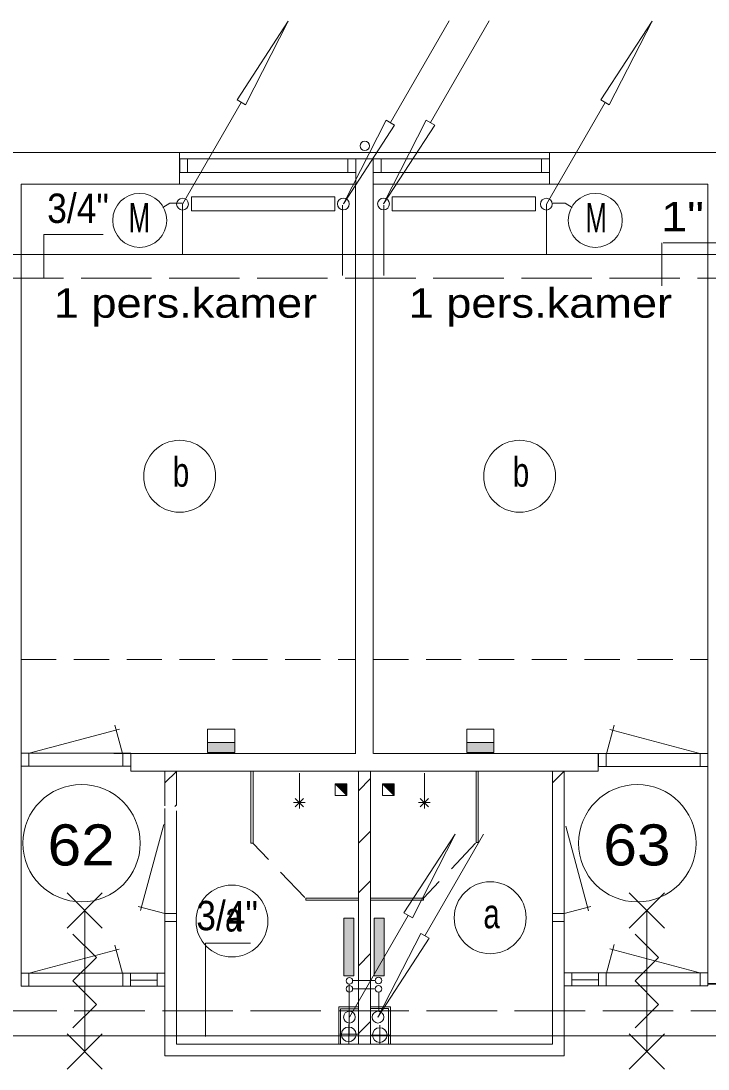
# Model space of a CAD drawing. Extents: x 295824 to 414724, y 24924 to 109024.
# Drawn here: x 308090 to 313941, y 39720 to 48648 of the extents above; entities that cross this region are included whole.
import ezdxf
from ezdxf.enums import TextEntityAlignment as Align

# ---------------------------------------------------------------- set-up
doc = ezdxf.new("R2010")
doc.units = 0
doc.header["$LTSCALE"] = 100
for name, pattern in [('DOT_DASHED', [7.7, 5, -1.2, 0.3, -1.2]), ('LONG_DASHED', [7.5, 6, -1.5]), ('MEDIUM_DASHED', [4.5, 3, -1.5])]:
    doc.linetypes.add(name, pattern=pattern)
doc.layers.add('16', color=7, linetype='Continuous', lineweight=13)
doc.layers.add('61', color=7, linetype='Continuous', lineweight=13)

msp = doc.modelspace()

# ---------------------------------------------------------------- hatches: boundary and pattern name
at = {"layer": '16'}
for points in [[(309911.3, 42415.9), (309679.8, 42415.9), (309679.8, 42502.4), (309911.3, 42502.4)], [(312117.3, 42415.9), (311885.8, 42415.9), (311885.8, 42502.4), (312117.3, 42502.4)], [(310838.6, 41005.7), (310924, 41005.7), (310924, 40513.5), (310838.6, 40513.5)], [(311097.8, 41005.7), (311183.2, 41005.7), (311183.2, 40513.5), (311097.8, 40513.5)]]:
    msp.add_hatch(color=256, dxfattribs=at).paths.add_polyline_path(points)
at = {"layer": '61'}
for points in [[(310864.9, 42048.6), (310764.9, 42148.6), (310864.9, 42148.6)], [(311267.9, 42048.6), (311167.9, 42148.6), (311267.9, 42148.6)]]:
    msp.add_hatch(color=256, dxfattribs=at).paths.add_polyline_path(points)

# ---------------------------------------------------------------- linework, layer by layer
at = {"layer": '16'}
for p, q in [((311735.8, 48648), (311235.8, 47782)), ((312077.5, 48648), (311577.5, 47782)), ((309465.8, 47087.9), (309965.8, 47953.9)), ((312564.3, 47087.9), (313064.3, 47953.9)), ((309466.3, 47084.3), (309466.3, 46658)), ((312564.8, 47084.3), (312564.8, 46658)), ((313547, 46391.6), (313547, 46759.1)), ((313558.7, 46759.1), (314063.8, 46759.1)), ((303410.7, 46658), (326194, 46658)), ((309466.3, 46658), (325376.7, 46658)), ((309679.8, 42502.4), (309679.8, 42616.3)), ((311885.8, 42502.4), (311885.8, 42616.3)), ((312030.4, 41720.5), (311530.4, 40854.5)), ((310887.4, 40162.2), (311387.4, 41028.2)), ((311106.2, 40474.7), (310914.5, 40474.7)), ((310885.9, 40002.8), (310885.9, 40439.3)), ((326194, 40002.8), (302570.9, 40002.8))]:
    msp.add_line(p, q, dxfattribs=at)
at = {"layer": '16', "linetype": 'LONG_DASHED'}
for p, q in [((310827, 47078.4), (310827, 46458)), ((311180.5, 47078.4), (311180.5, 46458)), ((304851.7, 46458), (326394, 46458)), ((310914.6, 40403.9), (311106.1, 40403.9)), ((311137.1, 40214.6), (311137.1, 40378.2)), ((326394, 40214.6), (302769.9, 40214.6))]:
    msp.add_line(p, q, dxfattribs=at)
at = {"layer": '16'}
for points in [[(310365.8, 48646.9), (310001.8, 47932.9), (309929.8, 47974.9)], [(313464.3, 48646.9), (313100.3, 47932.9), (313028.3, 47974.9)], [(310835.8, 47089), (311199.8, 47803), (311271.8, 47761)], [(311177.5, 47089), (311541.5, 47803), (311613.5, 47761)], [(309542.9, 47031.2), (310762.2, 47031.2), (310762.2, 47149.1), (309542.9, 47149.1)], [(311251.1, 47031.2), (312470.5, 47031.2), (312470.5, 47149.1), (311251.1, 47149.1)], [(309911.3, 42415.9), (309679.8, 42415.9), (309679.8, 42502.4), (309911.3, 42502.4)], [(312117.3, 42415.9), (311885.8, 42415.9), (311885.8, 42502.4), (312117.3, 42502.4)], [(311787.4, 41721.2), (311423.4, 41007.2), (311351.4, 41049.2)], [(310838.6, 41005.7), (310924, 41005.7), (310924, 40513.5), (310838.6, 40513.5)], [(311097.8, 41005.7), (311183.2, 41005.7), (311183.2, 40513.5), (311097.8, 40513.5)], [(311130.4, 40161.5), (311494.4, 40875.5), (311566.4, 40833.5)]]:
    msp.add_lwpolyline(points, close=True, dxfattribs=at)
for points in [[(309462.5, 47094.6), (309356.5, 47094.6), (309297, 47060.2)], [(312619.9, 47094.6), (312725.9, 47094.6), (312785.4, 47060.2)], [(308284.5, 46462.7), (308284.5, 46830.2), (308789.6, 46830.2)], [(309911.3, 42502.4), (309911.3, 42616.3), (309679.8, 42616.3)], [(312117.3, 42502.4), (312117.3, 42616.3), (311885.8, 42616.3)], [(309662, 39996.4), (309662, 40792.7), (310044.6, 40792.7)]]:
    msp.add_lwpolyline(points, dxfattribs=at)
for centre, radius in [((309101.4, 46949.2), 229.9), ((312981, 46949.2), 229.9), ((309465.7, 47087.6), 50), ((310835.8, 47089.3), 50), ((311177.5, 47089.3), 50), ((312564.3, 47087.6), 50), ((310886.7, 40471.7), 27.9), ((311134.1, 40474.6), 27.9), ((310886.7, 40403.9), 27.9), ((311134.1, 40403.9), 27.9), ((310887.4, 40161.9), 50), ((311130.4, 40161.8), 50)]:
    msp.add_circle(centre, radius, dxfattribs=at)
at = {"layer": '61'}
for p, q in [((301828.9, 47527.9), (333452, 47527.9)), ((309440.9, 47257.3), (309440.9, 47527.3)), ((312589.9, 47257.3), (312589.9, 47527.3)), ((313820.3, 47527.9), (333174.1, 47527.9)), ((309441.7, 47472.1), (310940.7, 47472.1)), ((309441.7, 47358.1), (309441.7, 47472.1)), ((309508.7, 47358.1), (309508.7, 47471.5)), ((310873.7, 47472.1), (312589.7, 47472.1)), ((310873.7, 47358.5), (310873.7, 47472.1)), ((310940.7, 47359.1), (310940.7, 47472.1)), ((310940.9, 47257.3), (310940.9, 47472.1)), ((311089.9, 47257.3), (311089.9, 47472.1)), ((311090.7, 47358.1), (311090.7, 47472.1)), ((311157.7, 47358.1), (311157.7, 47471.5)), ((312522.7, 47358.5), (312522.7, 47471.5)), ((312589.7, 47359.1), (312589.7, 47472.1)), ((309441.7, 47358.1), (310939.8, 47358.1)), ((311090.7, 47358.1), (312588.8, 47358.1)), ((308090.1, 40536.9), (308090.1, 47257.9)), ((313940.1, 40532.9), (313940.1, 47257.9)), ((308160.8, 42409.2), (308928.1, 42614.8)), ((308955.3, 42407.1), (308890.3, 42649.8)), ((313077.1, 42405.1), (313142.2, 42647.8)), ((313871.7, 42407.2), (313104.4, 42612.8)), ((308158.2, 42299.1), (308158.2, 42409.1)), ((308958.2, 42299.1), (308958.2, 42409.1)), ((309025.2, 42299.1), (309025.2, 42409.1)), ((310940.8, 42407.9), (308880.8, 42407.9)), ((311090.8, 42407.9), (313940.1, 42407.9)), ((311090.8, 42407.9), (313033.3, 42407.9)), ((313007.3, 42297.1), (313007.3, 42407.1)), ((313074.3, 42297.1), (313074.3, 42407.1)), ((313874.3, 42297.1), (313874.3, 42407.1)), ((313940.2, 42297.4), (313940.2, 42407.8)), ((309023.1, 42299.4), (308092.3, 42299.4)), ((309026.1, 42257.9), (312616.2, 42257.9)), ((309315.9, 41961), (309315.9, 42257.9)), ((309315.9, 42157.2), (309416.3, 42257.6)), ((309414.6, 41963.8), (309414.6, 42257.9)), ((310048.5, 41644.6), (310048.5, 42253)), ((310066.5, 41644.6), (310066.5, 42253)), ((310461.4, 42039.2), (310461.4, 42239.2)), ((310965.8, 42257.9), (310965.8, 41262.7)), ((311065.8, 42257.9), (311065.8, 41409)), ((311525.9, 42039.2), (311525.9, 42239.2)), ((311966.4, 41650.7), (311966.4, 42255.5)), ((311984.4, 41650.7), (311984.4, 42255.5)), ((312616.2, 41984), (312616.2, 42258.3)), ((312616.4, 42157.2), (312716.8, 42257.6)), ((312716, 41992.3), (312716, 42257.9)), ((313009.4, 42297.4), (313940.2, 42297.4)), ((310966.3, 42093), (311064.8, 42191.5)), ((309400.3, 41955.2), (309414.9, 41969.9)), ((310511.4, 41989.2), (310411.4, 41989.2)), ((310496.8, 42024.5), (310426.1, 41953.8)), ((310496.8, 41953.8), (310426.1, 42024.5)), ((310461.4, 42039.2), (310461.4, 41939.2)), ((311575.9, 41989.2), (311475.9, 41989.2)), ((311561.3, 42024.5), (311490.5, 41953.8)), ((311561.3, 41953.8), (311490.5, 42024.5)), ((311525.9, 42039.2), (311525.9, 41939.2)), ((312615.8, 42005.8), (312615.8, 40977.5)), ((312715.9, 41578.4), (312715.9, 42016.7)), ((309315.7, 40977.9), (309315.7, 41940.6)), ((309415.7, 41918.8), (309415.7, 40977.9)), ((309305.8, 41803.7), (309109, 41069.1)), ((312729.4, 41789.3), (312922.4, 41068.7)), ((310966.3, 41645.4), (311064.8, 41743.9)), ((310048.5, 41644.6), (310066.5, 41644.6)), ((310965.8, 41630.2), (310965.8, 39932.9)), ((311065.8, 41641.3), (311065.8, 39932.9)), ((311966.4, 41650.7), (311984.4, 41650.7)), ((312715.8, 40976.7), (312715.8, 41624.6)), ((310966.3, 41222.9), (311064.8, 41321.4)), ((308482.7, 40919.8), (308782.7, 41219.8)), ((308782.7, 40919.8), (308482.7, 41219.8)), ((311516.8, 41176.7), (311066.8, 41176.7)), ((311516.8, 41176.7), (311516.8, 41158.7)), ((313270.4, 40919.8), (313570.4, 41219.8)), ((313570.4, 40919.8), (313270.4, 41219.8)), ((308632.7, 41069.8), (308632.7, 39869.8)), ((309315.9, 41043.9), (309088.6, 41104.8)), ((310965.4, 41158.7), (310515.1, 41158.7)), ((311516.8, 41158.7), (311066.8, 41158.7)), ((312715.5, 41043.5), (312942.8, 41104.4)), ((313420.4, 41069.8), (313420.4, 39869.8)), ((309415.5, 41044.9), (309316.2, 41044.9)), ((312615.9, 41044.5), (312715.2, 41044.5)), ((309415.7, 40977.9), (309315.7, 40977.9)), ((309315.8, 40975.3), (309315.8, 40188.2)), ((309415.8, 40638.2), (309415.8, 40975.3)), ((312615.8, 40977.5), (312715.8, 40977.5)), ((312715.8, 40977.5), (312715.8, 40532.9)), ((308159.5, 40535.1), (308926.8, 40740.7)), ((308954.1, 40532.9), (308889.1, 40775.7)), ((313077.1, 40536.8), (313142.2, 40779.5)), ((313871.7, 40539), (313104.4, 40744.6)), ((310966.3, 40603), (311064.8, 40701.4)), ((308157, 40424.9), (308157, 40534.9)), ((308957, 40424.9), (308957, 40534.9)), ((309024, 40424.9), (309024, 40534.9)), ((309249.5, 40424.9), (309249.5, 40534.9)), ((312781.8, 40428.8), (312781.8, 40538.8)), ((313007.3, 40428.8), (313007.3, 40538.8)), ((313074.3, 40428.8), (313074.3, 40538.8)), ((313874.3, 40428.8), (313874.3, 40538.8)), ((309024.8, 40475.7), (309249.5, 40475.7)), ((313006.5, 40479.6), (312781.8, 40479.6)), ((313940.2, 40447.3), (314090.2, 40447.3)), ((309315.8, 40432.9), (309315.8, 39832.9)), ((312715.8, 39832.9), (312715.8, 40432.9)), ((313940.2, 40443.5), (314090.2, 40443.5)), ((310797.5, 40248.9), (310965.3, 40248.9)), ((310797.5, 40248.9), (310797.5, 39935.2)), ((310812.5, 40233.9), (310966.5, 40233.9)), ((310812.5, 40233.9), (310812.5, 39934.9)), ((311066.5, 40250.3), (311235.6, 40250.3)), ((311220.7, 40235.1), (311067.3, 40235.1)), ((311220.7, 39933.5), (311220.7, 40235.1)), ((311235.6, 39932.9), (311235.6, 40250.3)), ((310967.7, 40024.9), (311065, 40122.2)), ((308482.7, 39719.8), (308782.7, 40019.8)), ((308782.7, 39719.8), (308482.7, 40019.8)), ((313270.4, 39719.8), (313570.4, 40019.8)), ((313570.4, 39719.8), (313270.4, 40019.8)), ((311090.6, 39932.9), (311279.7, 39932.9)), ((311104.2, 39932.9), (312615.8, 39932.9)), ((309315.8, 39832.9), (311290.8, 39832.9)), ((311049.9, 39832.9), (312715.8, 39832.9))]:
    msp.add_line(p, q, dxfattribs=at)
at = {"layer": '61', "linetype": 'MEDIUM_DASHED'}
for p, q in [((308090.1, 43208.1), (310940.1, 43208.1)), ((311090.1, 43208.1), (313940.1, 43208.1)), ((310507.7, 41179.8), (310065.9, 41644.8)), ((311962, 41643.1), (311518, 41175.8))]:
    msp.add_line(p, q, dxfattribs=at)
at = {"layer": '61', "linetype": 'DOT_DASHED'}
for p, q in [((310881.4, 39934.8), (310881.4, 40098.9)), ((311145.3, 39934.3), (311145.3, 40093.7)), ((310970.6, 40016), (310806.6, 40016)), ((311230.4, 40008.6), (311066.3, 40008.6)), ((311230.5, 40008.6), (311066.5, 40008.6))]:
    msp.add_line(p, q, dxfattribs=at)
at = {"layer": '61'}
for points in [[(308090.1, 47257.9), (310940.1, 47257.9), (310940.1, 42407.9)], [(308090.2, 47257.9), (310940.2, 47257.9), (310940.2, 42407.9)], [(313940.1, 47257.9), (311090.1, 47257.9), (311090.1, 42407.9)], [(313940.2, 47257.9), (311090.2, 47257.9), (311090.2, 42407.9)], [(308092.3, 42299.4), (308092.3, 42409.8), (309025.6, 42409.8)], [(310940.8, 42407.9), (309026.1, 42407.9), (309026.1, 42257.9)], [(313006.9, 42407.8), (313006.9, 42257.9), (312601.5, 42257.9)], [(310764.9, 42148.6), (310864.9, 42148.6), (310864.9, 42048.6)], [(311167.9, 42148.6), (311267.9, 42148.6), (311267.9, 42048.6)], [(310965.4, 41176.7), (310515.1, 41176.7), (310515.1, 41158.7)], [(309415.8, 41158.7), (309415.8, 39932.9), (311295.8, 39932.9)], [(312615.8, 40977.5), (312615.8, 39932.9), (312615.8, 40882.9)], [(308532.7, 40869.8), (308732.7, 40669.8), (308532.7, 40469.8), (308732.7, 40269.8), (308532.7, 40069.8)], [(313320.4, 40869.8), (313520.4, 40669.8), (313320.4, 40469.8), (313520.4, 40269.8), (313320.4, 40069.8)]]:
    msp.add_lwpolyline(points, dxfattribs=at)
for points in [[(310764.9, 42148.6), (310764.9, 42048.6), (310864.9, 42048.6)], [(310864.9, 42048.6), (310764.9, 42148.6), (310864.9, 42148.6)], [(311167.9, 42148.6), (311167.9, 42048.6), (311267.9, 42048.6)], [(311267.9, 42048.6), (311167.9, 42148.6), (311267.9, 42148.6)], [(308091, 40425.3), (308091, 40535.6), (309315.4, 40535.6), (309315.4, 40425.3)], [(313940.2, 40429.1), (313940.2, 40539.5), (312715.9, 40539.5), (312715.9, 40429.1)]]:
    msp.add_lwpolyline(points, close=True, dxfattribs=at)
for centre, radius in [((311017.9, 47584.2), 40), ((309441.3, 44769.7), 306.3), ((312336.8, 44769.7), 306.3), ((308605.9, 41643.7), 500), ((313338.8, 41643.7), 500), ((309886.8, 40980.6), 306.3), ((312086.2, 41008.4), 306.3), ((310881.4, 40015.2), 62.5), ((311145.9, 40009.3), 62.5)]:
    msp.add_circle(centre, radius, dxfattribs=at)

# ---------------------------------------------------------------- texts
at = {"layer": '16'}
for s, width, p in [('3/4"', 0.9, (308313.5, 46927.5)), ('M', 0.65, (309007.3, 46846.2)), ('M', 0.65, (312897.9, 46846.2)), ('1"', 1.2, (313540.6, 46856.4)), ('3/4"', 0.9, (309583, 40902.3))]:
    msp.add_text(s, height=250, dxfattribs=dict(at, width=width)).set_placement(p)
at = {"layer": '61'}
for s, width, p in [('1 pers.kamer', 1.15, (308369.2, 46120.2)), ('1 pers.kamer', 1.15, (311391.4, 46120.2)), ('b', 0.75, (309383.3, 44680.6)), ('b', 0.75, (312278.8, 44680.6)), ('a', 0.75, (309828.8, 40891.4)), ('a', 0.75, (312028.2, 40919.2))]:
    msp.add_text(s, height=250, dxfattribs=dict(at, width=width)).set_placement(p)
at = {"layer": '61', "width": 1.1}
for s, p in [('62', (308602.9, 41453.9)), ('63', (313335.9, 41453.9))]:
    msp.add_text(s, height=350, dxfattribs=at).set_placement(p, align=Align.CENTER)

doc.saveas('drawing.dxf')
